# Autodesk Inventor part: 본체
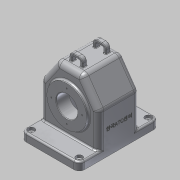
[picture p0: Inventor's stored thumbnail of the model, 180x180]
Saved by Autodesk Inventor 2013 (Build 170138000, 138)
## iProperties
Created: 2016-12
Part Number: 본체
Material: 알루미늄 6061
Document SubType Name: Modeling
Designer: Administrator
Density: 2.71 g/cm^3
Mass: 1067.65 g
Surface Area: 1138.93 cm^2
Volume: 393.966 cm^3
Author: Administrator
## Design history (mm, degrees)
sketch "스케치1"
  geometry: L1 (-55, -38.5)-(55, -38.5); L2 (55, -38.5)-(55, 38.5); L3 (55, 38.5)-(-55, 38.5); L4 (-55, 38.5)-(-55, -38.5); L5 (-55, -38.5)-(55, 38.5); L6 (55, -38.5)-(-55, 38.5); 1 further point
  constraints: 12 end point, 2 midpoint, 2 parallel, 1 horizontal, 1 perpendicular
  dimensions: "d0" = 110 distance of L1.start L1.end; "d2" = 77 distance of L3.end L1.start
extrude "돌출1" new body sketch "스케치1" distance "d3" = 125; taper "d4" = 0 deg
sketch "스케치2"
  geometry: L1 (0, 0)-(110, 0) reference; L2 (110, 0)-(110, 125) reference; L3 (0, 125)-(110, 125) reference; L4 (0, 0)-(0, 125) reference; L5 (0, 80)-(31.509, 125); L6 (78.491, 125)-(110, 80); 1 further point
  constraints: 4 end point, 4 point on line
  dimensions: "d5" = 35 deg angle of L5 L4; "d6" = 35 deg angle of L2 L6; "d7" = 80 distance from line of L1 L5.start; "d8" = 80 distance from line of L1 L6.end
extrude "돌출2" cut sketch "스케치2" stored distance "d9" = 125; taper "d10" = 0 deg
feature "쉘1" dims "d11" = 5
sketch "스케치3"
  geometry: L1 (0, 0)-(110, 0) reference; C1 r 37.5 at (55, 65); 2 further points
  constraints: 1 centre point, 1 midpoint, 1 vertical alignment
  dimensions: "d12" = 75 diameter of C1; "d14" = 65 distance from line of C1.centre L1
extrude "돌출3" join sketch "스케치3" distance "d15" = 5; taper "d16" = 0 deg
sketch "스케치4"
  geometry: L1 (110, 0)-(0, 0) reference; C1 r 31 at (55, -65); 2 further points
  constraints: 1 centre point, 1 midpoint, 1 vertical alignment
  dimensions: "d17" = 62 diameter of C1; "d19" = 65 distance from line of C1.centre L1
extrude "돌출4" join sketch "스케치4" distance "d20" = 10; taper "d21" = 0 deg
fillet "모깎기1" dims "d22" = 10
fillet "모깎기2" dims "d23" = 3
sketch "스케치5"
  geometry: L1 (-33.5, 117)-(-33.5, 77.478) reference; L2 (-33.5, 77.478)-(-33.5, 0) reference; L3 (-33.5, 106)-(-19.5, 92); L4 (-19.5, 92)-(-19.5, 85); L5 (-19.5, 85)-(-33.5, 85); L6 (33.5, 0)-(33.5, 77.478) reference; L7 (-33.5, 65)-(33.5, 65); L8 (-43.5, 102.5)-(-43.5, 27.5) reference; L9 (-33.5, 85)-(-33.5, 106); 1 further point
  constraints: 10 end point, 4 point on line, 2 parallel, 2 perpendicular
  dimensions: "d24" = 65 distance from line of point (0, 0) L7; "d25" = 24 distance between parallel lines of L4 L8; "d26" = 40 diameter of L5 L7; "d27" = 45 deg angle of L4 L3; "d28" = 54 diameter of L3.end L7
revolve "회전1" sketch "스케치5" stored, may be unused: angle "d29" = 90 deg
sketch "스케치6"
  geometry: C1 r 37.5 at (0, 0) reference; C2 r 20 at (0, 0); 1 further point
  constraints: 1 centre point, 1 coincident
  dimensions: "d30" = 40 diameter of C2
extrude "돌출5" cut sketch "스케치6" stored distance "d32" = 10; taper "d33" = 0 deg
fillet "모깎기3" dims "d34" = 3
sketch "스케치7"
  geometry: L1 (-55, -28.5)-(-55, 28.5) reference; L2 (45, -38.5)-(-45, -38.5) reference; L3 (55, 28.5)-(55, -28.5) reference; L4 (-45, 38.5)-(45, 38.5) reference; L5 (-55, -75)-(55, -75); L6 (55, -75)-(55, 75); L7 (55, 75)-(-55, 75); L8 (-55, 75)-(-55, -75); L9 (-55, -75)-(55, 75); L10 (55, -75)-(-55, 75); A1 r 10 centre (-45, 28.5) between (-45, 38.5) and (-55, 28.5) reference; A2 r 10 centre (-45, -28.5) between (-55, -28.5) and (-45, -38.5) reference; A3 r 10 centre (45, -28.5) between (45, -38.5) and (55, -28.5) reference; A4 r 10 centre (45, 28.5) between (55, 28.5) and (45, 38.5) reference; 1 further point
  constraints: 12 end point, 2 midpoint, 2 parallel, 1 horizontal, 1 perpendicular
  dimensions: "d35" = 110 distance of L6.end L7.end; "d37" = 150 distance of L7.end L5.start
extrude "돌출6" join sketch "스케치7" distance "d38" = 15; taper "d39" = 0 deg
fillet "모깎기4" dims "d40" = 10
sketch "스케치8"
  geometry: A1 r 10 centre (45, 65) between (55, 65) and (45, 75) reference; A2 r 10 centre (-45, 65) between (-45, 75) and (-55, 65) reference; A3 r 10 centre (-45, -65) between (-55, -65) and (-45, -75) reference; A4 r 10 centre (45, -65) between (45, -75) and (55, -65) reference; 1 further point
hole "구멍1" sketch "스케치8" at (-45, 65), (-45, -65), (45, -65), (45, 65) diameter "d41" = 5; stored, may be unused: countersink angle "d45" = 90 deg, drill point angle "d47" = 0 deg; dims "d42" = 6, "d43" = 12, "d44" = 5, "d46" = 8
fillet "모깎기5" dims "d48" = 3
sketch "스케치9"
  geometry: L1 (-12.5, -26)-(12.5, -26); L2 (12.5, -26)-(12.5, -18); L3 (12.5, -18)-(-12.5, -18); L4 (-12.5, -18)-(-12.5, -26); L5 (-12.5, -26)-(12.5, -18); L6 (12.5, -26)-(-12.5, -18); L7 (-12.5, 18)-(12.5, 18); L8 (12.5, 18)-(12.5, 26); L9 (12.5, 26)-(-12.5, 26); L10 (-12.5, 26)-(-12.5, 18); L11 (-12.5, 18)-(12.5, 26); L12 (12.5, 18)-(-12.5, 26); 5 further points
  constraints: 24 end point, 6 midpoint, 4 parallel, 2 horizontal, 2 perpendicular, 2 vertical alignment
  dimensions: "d49" = 36 distance between parallel lines of L3 L7; "d51" = 18 distance from line of point (0, 0) L7; "d52" = 52 distance between parallel lines of L1 L9; "d53" = 25 distance between parallel lines of L2 L4; "d54" = 25 distance between parallel lines of L8 L10; "d55" = 26 distance from line of point (0, 0) L9
extrude "돌출7" join sketch "스케치9" distance "d56" = 15; taper "d57" = 0 deg
sketch "스케치10"
  geometry: L1 (25, 0)-(0, 0) reference; L2 (0, 15)-(25, 15) reference; L3 (5, 10)-(20, 10); L4 (20, 10)-(20, 0); L5 (20, 0)-(5, 0); L6 (5, 0)-(5, 10); C1 r 20 at (12.5, -60) reference; 1 further point
  constraints: 8 end point, 2 parallel, 1 horizontal, 1 perpendicular, 1 point on line
  dimensions: "d58" = 15 distance between parallel lines of L4 L6; "d60" = 7.5 distance from line of C1.centre L6; "d61" = 5 distance between parallel lines of L3 L2
extrude "돌출8" cut sketch "스케치10" stored distance "d62" = 15; taper "d63" = 0 deg
sketch "스케치11"
  geometry: C1 r 20 at (0, 0) reference; 2 further points
  constraints: 1 vertical alignment
  dimensions: "d70" = 29 distance of C1.centre point (0, 29)
hole "구멍2" sketch "스케치11" at (0, 29) diameter "d71" = 2.459; stored, may be unused: countersink angle "d75" = 90 deg, drill point angle "d77" = 118 deg; dims "d72" = 6, "d73" = 12, "d74" = 5, "d76" = 8
sketch "스케치12"
  geometry: C1 r 20 at (0, 0) reference; 2 further points
  constraints: 1 vertical alignment
  dimensions: "d81" = 26 distance of C1.centre point (0, 26)
hole "구멍3" sketch "스케치12" at (0, 26) diameter "d82" = 2.459; stored, may be unused: countersink angle "d86" = 90 deg, drill point angle "d88" = 118 deg; dims "d83" = 6, "d84" = 12, "d85" = 5, "d87" = 8
sketch "스케치13"
  geometry: L1 (76.847, 93.5)-(76.847, -36.5) reference; L2 (44.429, 3.613)-(44.429, 53.387); L3 (44.429, 53.387)-(19.265, 53.387); L4 (19.265, 53.387)-(19.265, 3.613); L5 (19.265, 3.613)-(44.429, 3.613); L6 (44.429, 28.5)-(19.265, 28.5); L7 (31.847, 3.613)-(31.847, 53.387); L8 (0, -10)-(58.847, -10) reference; 2 further points
  constraints: 5 midpoint, 4 end point, 2 other
  dimensions: "d92" = 45 distance between parallel lines of L1 L7; "d93" = 38.5 distance between parallel lines of L6 L8
extrude "돌출9" join sketch "스케치13" distance "d94" = 0.5; taper "d95" = 0 deg
fillet "모깎기12" dims "d96" = 8, "d97" = 3
fillet "모깎기13" dims "d98" = 1
chamfer "모따기1" distance "d99" = 1; stored, may be unused: second distance "d100" = 2, angle "d101" = 45 deg
node "솔리드1"
pattern_circular "원형 패턴1" dims angle "d79" = 360 deg
pattern_circular "원형 패턴2" dims angle "d90" = 360 deg
